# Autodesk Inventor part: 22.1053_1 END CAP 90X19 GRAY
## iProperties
Created: 2007-01
Part Number: 22.1053_1 END CAP 90X19 GRAY
Document SubType Name: Modeling
Designer: Andy Moles
Material: ABS Plastic
Density: 1.06 g/cm^3
Author: Andy Moles
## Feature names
1. Extrusion1
2. Fillet1
3. Fillet2
4. Extrusion2
5. Fillet3
